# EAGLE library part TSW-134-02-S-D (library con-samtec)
THROUGH-HOLE .025" SQ POST HEADER Source: Samtec TSW.pdf
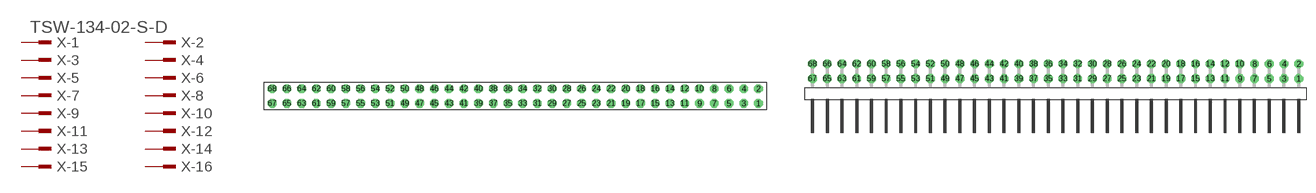
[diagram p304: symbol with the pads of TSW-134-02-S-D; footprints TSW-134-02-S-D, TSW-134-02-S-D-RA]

Designator prefix X; gates -1=MPINV -2=MPIN -3=MPIN -4=MPIN -5=MPIN -6=MPIN -7=MPIN -8=MPIN -9=MPIN -10=MPIN -11=MPIN -12=MPIN -13=MPIN -14=MPIN -15=MPIN -16=MPIN -17=MPIN -18=MPIN -19=MPIN -20=MPIN -21=MPIN -22=MPIN -23=MPIN -24=MPIN -25=MPIN -26=MPIN -27=MPIN -28=MPIN -29=MPIN -30=MPIN -31=MPIN -32=MPIN -33=MPIN -34=MPIN -35=MPIN -36=MPIN -37=MPIN -38=MPIN -39=MPIN -40=MPIN -41=MPIN -42=MPIN -43=MPIN -44=MPIN -45=MPIN -46=MPIN -47=MPIN -48=MPIN -49=MPIN -50=MPIN -51=MPIN -52=MPIN -53=MPIN -54=MPIN -55=MPIN -56=MPIN -57=MPIN -58=MPIN -59=MPIN -60=MPIN -61=MPIN -62=MPIN -63=MPIN -64=MPIN -65=MPIN -66=MPIN -67=MPIN -68=MPIN

## TSW-134-02-S-D (OC_FARNELL: unknown; OC_NEWARK: unknown)  [TSW-134-02-S-D]
1  -1:1  pas
2  -2:1  pas
3  -3:1  pas
4  -4:1  pas
5  -5:1  pas
6  -6:1  pas
7  -7:1  pas
8  -8:1  pas
9  -9:1  pas
10  -10:1  pas
11  -11:1  pas
12  -12:1  pas
13  -13:1  pas
14  -14:1  pas
15  -15:1  pas
16  -16:1  pas
17  -17:1  pas
18  -18:1  pas
19  -19:1  pas
20  -20:1  pas
21  -21:1  pas
22  -22:1  pas
23  -23:1  pas
24  -24:1  pas
25  -25:1  pas
26  -26:1  pas
27  -27:1  pas
28  -28:1  pas
29  -29:1  pas
30  -30:1  pas
31  -31:1  pas
32  -32:1  pas
33  -33:1  pas
34  -34:1  pas
35  -35:1  pas
36  -36:1  pas
37  -37:1  pas
38  -38:1  pas
39  -39:1  pas
40  -40:1  pas
41  -41:1  pas
42  -42:1  pas
43  -43:1  pas
44  -44:1  pas
45  -45:1  pas
46  -46:1  pas
47  -47:1  pas
48  -48:1  pas
49  -49:1  pas
50  -50:1  pas
51  -51:1  pas
52  -52:1  pas
53  -53:1  pas
54  -54:1  pas
55  -55:1  pas
56  -56:1  pas
57  -57:1  pas
58  -58:1  pas
59  -59:1  pas
60  -60:1  pas
61  -61:1  pas
62  -62:1  pas
63  -63:1  pas
64  -64:1  pas
65  -65:1  pas
66  -66:1  pas
67  -67:1  pas
68  -68:1  pas

## TSW-134-02-S-D-RA (OC_FARNELL: unknown; OC_NEWARK: unknown)  [TSW-134-02-S-D-RA]
Pads as for TSW-134-02-S-D

## Footprint TSW-134-02-S-D (pad centres in mm)
THROUGH-HOLE .025" SQ POST HEADER Source: Samtec TSW.pdf
drill 1 pad 1.5 octagon: 1 41.91,-1.27; 2 41.91,1.27; 3 39.37,-1.27; 4 39.37,1.27; 5 36.83,-1.27; 6 36.83,1.27; 7 34.29,-1.27; 8 34.29,1.27; 9 31.75,-1.27; 10 31.75,1.27; 11 29.21,-1.27; 12 29.21,1.27; 13 26.67,-1.27; 14 26.67,1.27; 15 24.13,-1.27; 16 24.13,1.27; 17 21.59,-1.27; 18 21.59,1.27; 19 19.05,-1.27; 20 19.05,1.27; 21 16.51,-1.27; 22 16.51,1.27; 23 13.97,-1.27; 24 13.97,1.27; 25 11.43,-1.27; 26 11.43,1.27; 27 8.89,-1.27; 28 8.89,1.27; 29 6.35,-1.27; 30 6.35,1.27; 31 3.81,-1.27; 32 3.81,1.27; 33 1.27,-1.27; 34 1.27,1.27; 35 -1.27,-1.27; 36 -1.27,1.27; 37 -3.81,-1.27; 38 -3.81,1.27; 39 -6.35,-1.27; 40 -6.35,1.27; 41 -8.89,-1.27; 42 -8.89,1.27; 43 -11.43,-1.27; 44 -11.43,1.27; 45 -13.97,-1.27; 46 -13.97,1.27; 47 -16.51,-1.27; 48 -16.51,1.27; 49 -19.05,-1.27; 50 -19.05,1.27; 51 -21.59,-1.27; 52 -21.59,1.27; 53 -24.13,-1.27; 54 -24.13,1.27; 55 -26.67,-1.27; 56 -26.67,1.27; 57 -29.21,-1.27; 58 -29.21,1.27; 59 -31.75,-1.27; 60 -31.75,1.27; 61 -34.29,-1.27; 62 -34.29,1.27; 63 -36.83,-1.27; 64 -36.83,1.27; 65 -39.37,-1.27; 66 -39.37,1.27; 67 -41.91,-1.27; 68 -41.91,1.27

## Footprint TSW-134-02-S-D-RA (pad centres in mm)
THROUGH-HOLE .025" SQ POST HEADER Source: Samtec TSW.pdf
drill 1 pad 1.5 octagon: 1 41.91,1.524; 2 41.91,4.064; 3 39.37,1.524; 4 39.37,4.064; 5 36.83,1.524; 6 36.83,4.064; 7 34.29,1.524; 8 34.29,4.064; 9 31.75,1.524; 10 31.75,4.064; 11 29.21,1.524; 12 29.21,4.064; 13 26.67,1.524; 14 26.67,4.064; 15 24.13,1.524; 16 24.13,4.064; 17 21.59,1.524; 18 21.59,4.064; 19 19.05,1.524; 20 19.05,4.064; 21 16.51,1.524; 22 16.51,4.064; 23 13.97,1.524; 24 13.97,4.064; 25 11.43,1.524; 26 11.43,4.064; 27 8.89,1.524; 28 8.89,4.064; 29 6.35,1.524; 30 6.35,4.064; 31 3.81,1.524; 32 3.81,4.064; 33 1.27,1.524; 34 1.27,4.064; 35 -1.27,1.524; 36 -1.27,4.064; 37 -3.81,1.524; 38 -3.81,4.064; 39 -6.35,1.524; 40 -6.35,4.064; 41 -8.89,1.524; 42 -8.89,4.064; 43 -11.43,1.524; 44 -11.43,4.064; 45 -13.97,1.524; 46 -13.97,4.064; 47 -16.51,1.524; 48 -16.51,4.064; 49 -19.05,1.524; 50 -19.05,4.064; 51 -21.59,1.524; 52 -21.59,4.064; 53 -24.13,1.524; 54 -24.13,4.064; 55 -26.67,1.524; 56 -26.67,4.064; 57 -29.21,1.524; 58 -29.21,4.064; 59 -31.75,1.524; 60 -31.75,4.064; 61 -34.29,1.524; 62 -34.29,4.064; 63 -36.83,1.524; 64 -36.83,4.064; 65 -39.37,1.524; 66 -39.37,4.064; 67 -41.91,1.524; 68 -41.91,4.064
